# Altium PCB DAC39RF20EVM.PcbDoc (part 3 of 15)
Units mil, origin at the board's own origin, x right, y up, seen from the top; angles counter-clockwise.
Board outline 6200 x 2716.54 mil, 16 copper layers (Top Layer, L2 GND, L3 PWR, L4 GND, L5 PWR, L6 GND, L7 SIG, L8 GND, L9 GND, L10 SIG, L11 GND, L12 PWR, L13 GND, L14 PWR, L15 GND, Bottom Layer), stack 76.97 mil thick; 766 components, 495 nets, 3414 pads, 2373 vias.
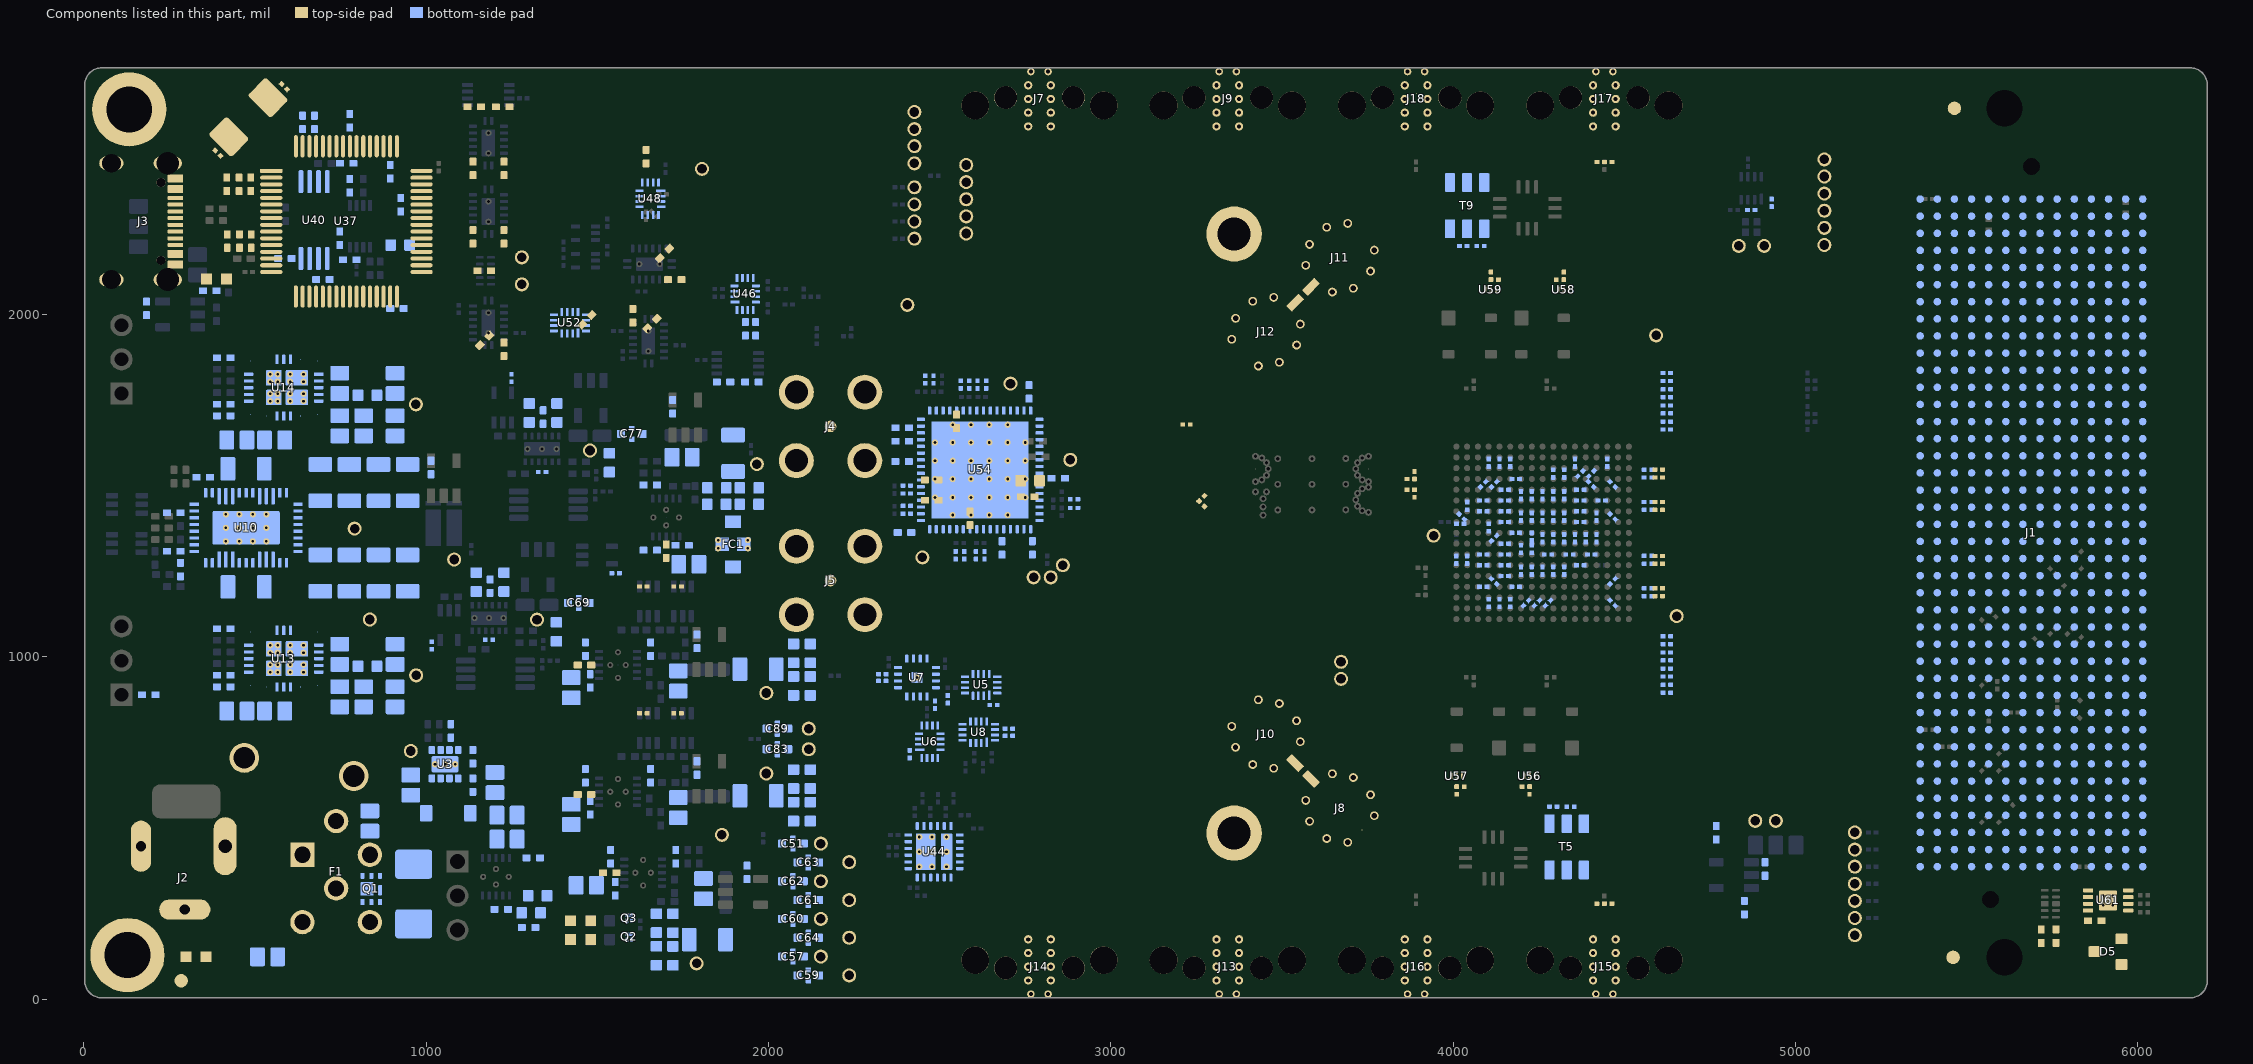
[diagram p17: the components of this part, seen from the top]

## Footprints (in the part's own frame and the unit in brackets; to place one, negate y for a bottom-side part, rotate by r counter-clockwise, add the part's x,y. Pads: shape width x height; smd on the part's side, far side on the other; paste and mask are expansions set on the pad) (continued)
HiRose-HK-LR-SR2-SWM1092-04A-MicroStirp-6mil-Female-Backdrill [mil]
  round 1 smd paste-100 mask+1.97: 1(75,0)
  round 22 hole 12 mask+1.97: 2(11,-25) 3(11,25)
  round 24 hole 12 mask+1.97: 2(51,-33) 2(91,-33) 3(51,33) 3(91,33) 3(131,-33) 3(131,33) 3(171,-33) 3(171,33)
  round 1 smd mask+1.97: 2(93.75,-131.66) 3(93.75,131.66)
  round 81 hole 81 mask+15.75: 2(110,-187.5) 3(110,187.5)
  round 1 on Mid1 mask+2.76: 3(86.25,0)
  round 66.93 hole 66.93 mask+15.75: 4(87,98.5) 4(87,-98.5)
  Top Layer region: 0,3.5 50,6.15 150,6.15 150,-6.15 50,-6.15 0,-3.5
  Top Layer region: 0,-249.82 0,-13.5 11.24,-13.5 14.57,-14.16 17.4,-16.05 17.4,-16.05 22.5,-21.15 187.5,-21.15 187.5,-249.82
  Top Layer region: 0,249.83 0,13.5 11.24,13.5 14.57,14.16 17.4,16.05 17.4,16.05 22.5,21.15 187.5,21.15 187.5,249.83
  L2 GND pour cut-out: 157,33 158.07,27.64 161.1,23.1 165.64,20.07 171,19 171,19 176.36,20.07 180.9,23.1 183.93,27.64 185,33 185,33 183.93,38.36 180.9,42.9 176.36,45.93 171,47 171,47 165.64,45.93 161.1,42.9 158.07,38.36 157,33
  L2 GND pour cut-out: 157,-33 158.07,-38.36 161.1,-42.9 165.64,-45.93 171,-47 171,-47 176.36,-45.93 180.9,-42.9 183.93,-38.36 185,-33 185,-33 183.93,-27.64 180.9,-23.1 176.36,-20.07 171,-19 171,-19 165.64,-20.07 161.1,-23.1 158.07,-27.64 157,-33
  L2 GND pour cut-out: 117,33 118.07,27.64 121.1,23.1 125.64,20.07 131,19 131,19 136.36,20.07 140.9,23.1 143.93,27.64 145,33 145,33 143.93,38.36 140.9,42.9 136.36,45.93 131,47 131,47 125.64,45.93 121.1,42.9 118.07,38.36 117,33
  L2 GND pour cut-out: 117,-33 118.07,-38.36 121.1,-42.9 125.64,-45.93 131,-47 131,-47 136.36,-45.93 140.9,-42.9 143.93,-38.36 145,-33 145,-33 143.93,-27.64 140.9,-23.1 136.36,-20.07 131,-19 131,-19 125.64,-20.07 121.1,-23.1 118.07,-27.64 117,-33
  L2 GND pour cut-out: 77,33 78.07,27.64 81.1,23.1 85.64,20.07 91,19 91,19 96.36,20.07 100.9,23.1 103.93,27.64 105,33 105,33 103.93,38.36 100.9,42.9 96.36,45.93 91,47 91,47 85.64,45.93 81.1,42.9 78.07,38.36 77,33
  L2 GND pour cut-out: 77,-33 78.07,-38.36 81.1,-42.9 85.64,-45.93 91,-47 91,-47 96.36,-45.93 100.9,-42.9 103.93,-38.36 105,-33 105,-33 103.93,-27.64 100.9,-23.1 96.36,-20.07 91,-19 91,-19 85.64,-20.07 81.1,-23.1 78.07,-27.64 77,-33
  L2 GND pour cut-out: 37,33 38.07,27.64 41.1,23.1 45.64,20.07 51,19 51,19 56.36,20.07 60.9,23.1 63.93,27.64 65,33 65,33 63.93,38.36 60.9,42.9 56.36,45.93 51,47 51,47 45.64,45.93 41.1,42.9 38.07,38.36 37,33
  L2 GND pour cut-out: 37,-33 38.07,-38.36 41.1,-42.9 45.64,-45.93 51,-47 51,-47 56.36,-45.93 60.9,-42.9 63.93,-38.36 65,-33 65,-33 63.93,-27.64 60.9,-23.1 56.36,-20.07 51,-19 51,-19 45.64,-20.07 41.1,-23.1 38.07,-27.64 37,-33
  L2 GND pour cut-out: -3,25 -1.93,19.64 1.1,15.1 5.64,12.07 11,11 11,11 16.36,12.07 20.9,15.1 23.93,19.64 25,25 25,25 23.93,30.36 20.9,34.9 16.36,37.93 11,39 11,39 5.64,37.93 1.1,34.9 -1.93,30.36 -3,25
  L2 GND pour cut-out: -3,-25 -1.93,-30.36 1.1,-34.9 5.64,-37.93 11,-39 11,-39 16.36,-37.93 20.9,-34.9 23.93,-30.36 25,-25 25,-25 23.93,-19.64 20.9,-15.1 16.36,-12.07 11,-11 11,-11 5.64,-12.07 1.1,-15.1 -1.93,-19.64 -3,-25
  L2 GND region: 187.5,-249.82 187.5,249.83 -15,249.83 -15,-249.82
  Bottom Layer pour cut-out: 171,16 164.49,17.29 158.98,20.98 155.29,26.49 154,33 154,33 155.29,39.51 158.98,45.02 164.49,48.71 171,50 171,50 177.51,48.71 183.02,45.02 186.71,39.51 188,33 188,33 186.71,26.49 183.02,20.98 177.51,17.29 171,16
  Bottom Layer pour cut-out: 171,-50 164.49,-48.71 158.98,-45.02 155.29,-39.51 154,-33 154,-33 155.29,-26.49 158.98,-20.98 164.49,-17.29 171,-16 171,-16 177.51,-17.29 183.02,-20.98 186.71,-26.49 188,-33 188,-33 186.71,-39.51 183.02,-45.02 177.51,-48.71 171,-50
  Bottom Layer pour cut-out: 131,-50 124.49,-48.71 118.98,-45.02 115.29,-39.51 114,-33 114,-33 115.29,-26.49 118.98,-20.98 124.49,-17.29 131,-16 131,-16 137.51,-17.29 143.02,-20.98 146.71,-26.49 148,-33 148,-33 146.71,-39.51 143.02,-45.02 137.51,-48.71 131,-50
  Bottom Layer pour cut-out: 91,-50 84.49,-48.71 78.98,-45.02 75.29,-39.51 74,-33 74,-33 75.29,-26.49 78.98,-20.98 84.49,-17.29 91,-16 91,-16 97.51,-17.29 103.02,-20.98 106.71,-26.49 108,-33 108,-33 106.71,-39.51 103.02,-45.02 97.51,-48.71 91,-50
  Bottom Layer pour cut-out: 51,-50 44.49,-48.71 38.98,-45.02 35.29,-39.51 34,-33 34,-33 35.29,-26.49 38.98,-20.98 44.49,-17.29 51,-16 51,-16 57.51,-17.29 63.02,-20.98 66.71,-26.49 68,-33 68,-33 66.71,-39.51 63.02,-45.02 57.51,-48.71 51,-50
  Bottom Layer pour cut-out: 51,16 44.49,17.29 38.98,20.98 35.29,26.49 34,33 34,33 35.29,39.51 38.98,45.02 44.49,48.71 51,50 51,50 57.51,48.71 63.02,45.02 66.71,39.51 68,33 68,33 66.71,26.49 63.02,20.98 57.51,17.29 51,16
  Bottom Layer pour cut-out: 91,16 84.49,17.29 78.98,20.98 75.29,26.49 74,33 74,33 75.29,39.51 78.98,45.02 84.49,48.71 91,50 91,50 97.51,48.71 103.02,45.02 106.71,39.51 108,33 108,33 106.71,26.49 103.02,20.98 97.51,17.29 91,16
  Bottom Layer pour cut-out: 131,16 124.49,17.29 118.98,20.98 115.29,26.49 114,33 114,33 115.29,39.51 118.98,45.02 124.49,48.71 131,50 131,50 137.51,48.71 143.02,45.02 146.71,39.51 148,33 148,33 146.71,26.49 143.02,20.98 137.51,17.29 131,16
  Bottom Layer pour cut-out: 11,-42 4.49,-40.71 -1.02,-37.02 -4.71,-31.51 -6,-25 -6,-25 -4.71,-18.49 -1.02,-12.98 4.49,-9.29 11,-8 11,-8 17.51,-9.29 23.02,-12.98 26.71,-18.49 28,-25 28,-25 26.71,-31.51 23.02,-37.02 17.51,-40.71 11,-42
  Bottom Layer pour cut-out: 11,8 4.49,9.29 -1.02,12.98 -4.71,18.49 -6,25 -6,25 -4.71,31.51 -1.02,37.02 4.49,40.71 11,42 11,42 17.51,40.71 23.02,37.02 26.71,31.51 28,25 28,25 26.71,18.49 23.02,12.98 17.51,9.29 11,8
  body extent -376,-165 157,165, height 132
IEC_HotSurface_Small [mil]
  silkscreen extent -107,-93 107,92
Keystone5010 [mil] "Keystone Multipurpose loops"
  round 87 hole 63: 1(0,0)
  silkscreen extent -70,-70 70,70, body extent -63,-63 63,62, height 319
Keystone5125 [mil] "Keystone Multipurpose loops"
  round 87 hole 63: 1(0,0)
  silkscreen extent -70,-70 70,70, body extent -63,-63 63,62, height 319
Keystone_1797B [mm] "HEX STANDOFF 2-56 ALUMINUM 1/4\""
  round 4.1 hole 2.45 unplated mask+0: 4(0,0)
  body extent -2.29,-2.22 2.29,2.22, height 6.35
Label_650x200 [mil] "Thermal Transfer Label"
  silkscreen extent -325,-100 325,100
LED_LTST-C190-Green [mm] "Lite-On"
  rect 0.8x0.8 smd: 1(-0.75,0) 2(0.75,0)
  silkscreen extent -1.1,-0.8 1.8,0.8, body extent -0.85,-0.45 0.85,0.45, height 0.91
LED_LTST-C190-Red [mm] "Lite-On"
  rect 0.8x0.8 smd: 1(-0.75,0) 2(0.75,0)
  silkscreen extent -1.1,-0.8 1.8,0.8, body extent -0.85,-0.45 0.85,0.45, height 0.91
LQFP64-MFG [mm]
  rrect33% 1.65x0.3 smd paste+0 mask+0.05: 1(-5.575,3.75)
  rrect100% 1.65x0.3 smd paste+0 mask+0.05: 2(-5.575,3.25) 3(-5.575,2.75) 4(-5.575,2.25) 5(-5.575,1.75) 6(-5.575,1.25) 7(-5.575,0.75) 8(-5.575,0.25) 9(-5.575,-0.25) 10(-5.575,-0.75) 11(-5.575,-1.25) 12(-5.575,-1.75) 13(-5.575,-2.25) 14(-5.575,-2.75) 15(-5.575,-3.25) 16(-5.575,-3.75) 33(5.575,-3.75) 34(5.575,-3.25) 35(5.575,-2.75) 36(5.575,-2.25) 37(5.575,-1.75) 38(5.575,-1.25) 39(5.575,-0.75) 40(5.575,-0.25) 41(5.575,0.25) 42(5.575,0.75) 43(5.575,1.25) 44(5.575,1.75) 45(5.575,2.25) 46(5.575,2.75) 47(5.575,3.25) 48(5.575,3.75)
  rrect100% 0.3x1.65 smd paste+0 mask+0.05: 17(-3.75,-5.575) 18(-3.25,-5.575) 19(-2.75,-5.575) 20(-2.25,-5.575) 21(-1.75,-5.575) 22(-1.25,-5.575) 23(-0.75,-5.575) 24(-0.25,-5.575) 25(0.25,-5.575) 26(0.75,-5.575) 27(1.25,-5.575) 28(1.75,-5.575) 29(2.25,-5.575) 30(2.75,-5.575) 31(3.25,-5.575) 32(3.75,-5.575) 49(3.75,5.575) 50(3.25,5.575) 51(2.75,5.575) 52(2.25,5.575) 53(1.75,5.575) 54(1.25,5.575) 55(0.75,5.575) 56(0.25,5.575) 57(-0.25,5.575) 58(-0.75,5.575) 59(-1.25,5.575) 60(-1.75,5.575) 61(-2.25,5.575) 62(-2.75,5.575) 63(-3.25,5.575) 64(-3.75,5.575)
  silkscreen extent -7.12,-5.05 5.05,5.05, body extent -6.5,-6.5 6.5,6.5, height 0.25
MABA-011108 [mm]
  rrect20% 1.4x0.76 smd mask+0.05: 1(-1.715,1.27) 2(-1.715,0) 3(-1.715,-1.27) 4(1.715,-1.27) 5(1.715,0) 6(1.715,1.27)
  silkscreen extent -2.25,1.85 -2.15,1.95, body extent -1.91,-1.91 1.91,1.91, height 3.42
Molex_0853050232 [mm] "Plug, 50 Ohm, Straight, SMT"
  rrect17% 0.6x1.3 smd: 1(0,0)
  round 0.654 hole 0.4 mask+0.05: 2(-2.3,-2.15) 2(-2.3,-3.95) 2(-1.4,-5.25) 2(-1.4,-0.85) 2(1.4,-5.25) 2(1.4,-0.85) 2(2.3,-2.15) 2(2.3,-3.95)
  round 0.025 smd: 2(0,-5.35)
  Top Layer pour cut-out: -0.33,0.699 -0.33,-0.698 0.33,-0.698 0.33,0.698
  Top Layer pour cut-out: 0.998,-1.315 0.998,-0.45 -0.998,-0.45 -0.998,-1.321 -1.679,-1.973 -1.986,-2.865 -1.849,-3.798 -1.3,-4.565 -0.461,-4.995 0.482,-4.992 1.319,-4.557 1.864,-3.787 1.995,-2.854 1.683,-1.963 0.998,-1.315
  Top Layer region: -2.6,-5.65 -2.6,-0.45 -1,-0.45 -1,-1.318 -1.732,-2.05 -2,-3.05 -1.732,-4.05 -1,-4.782 0,-5.05 1,-4.782 1.732,-4.05 2,-3.05 1.732,-2.05 1,-1.318 1,-1.318 1,-0.45 2.6,-0.45 2.6,-5.65
  L2 GND pour cut-out: -0.33,0.699 -0.33,-0.698 0.33,-0.698 0.33,0.698
  L2 GND pour cut-out: 0.998,-1.315 0.998,-0.45 -0.998,-0.45 -0.998,-1.321 -1.679,-1.973 -1.986,-2.865 -1.849,-3.798 -1.3,-4.565 -0.461,-4.995 0.482,-4.992 1.319,-4.557 1.864,-3.787 1.995,-2.854 1.683,-1.963 0.998,-1.315
  L2 GND pour cut-out: 0.998,-1.315 0.998,-0.45 -0.998,-0.45 -0.998,-1.321 -1.679,-1.973 -1.986,-2.865 -1.849,-3.798 -1.3,-4.565 -0.461,-4.995 0.482,-4.992 1.319,-4.557 1.864,-3.787 1.995,-2.854 1.683,-1.963 0.998,-1.315
  L3 PWR pour cut-out: 0.998,-1.315 0.998,-0.45 -0.998,-0.45 -0.998,-1.321 -1.679,-1.973 -1.986,-2.865 -1.849,-3.798 -1.3,-4.565 -0.461,-4.995 0.482,-4.992 1.319,-4.557 1.864,-3.787 1.995,-2.854 1.683,-1.963 0.998,-1.315
  body extent -2.5,-5.55 2.5,0.45, height 4.1
NFM18PC [mm]
  rrect20% 0.6x0.6 smd mask+0.05: 1(-0.8,0) 3(0.8,0)
  rrect20% 0.4x0.4 smd mask+0.05: 2(0,-0.4) 2(0,0.4)
  body extent -0.8,-0.4 0.8,0.4, height 1.35
NFM31PC [mm]
  rrect10% 0.95x1.2 smd paste+0: 1(-1.675,0) 3(1.675,0)
  round 0.2 / inner round 0.454 / far side round 0.454 hole 0.2 mask+0.05: 2(-0.305,-1.105) 2(-0.305,1.105) 2(0.305,-1.105) 2(0.305,1.105)
  rrect10% 1x1 smd paste+0: 2(0,-0.8) 2(0,0.8)
  body extent -1.7,-0.9 1.7,0.9, height 1.5
NKD0064A [mm] "QFN, 64-Leads, Body 9x9mm, Pitch 0.5mm"
  rrect40% 0.6x0.25 smd mask+0.07: 1(-4.4,3.75) 2(-4.4,3.25) 3(-4.4,2.75) 4(-4.4,2.25) 5(-4.4,1.75) 6(-4.4,1.25) 7(-4.4,0.75) 8(-4.4,0.25) 9(-4.4,-0.25) 10(-4.4,-0.75) 11(-4.4,-1.25) 12(-4.4,-1.75) 13(-4.4,-2.25) 14(-4.4,-2.75) 15(-4.4,-3.25) 16(-4.4,-3.75) 33(4.4,-3.75) 34(4.4,-3.25) 35(4.4,-2.75) 36(4.4,-2.25) 37(4.4,-1.75) 38(4.4,-1.25) 39(4.4,-0.75) 40(4.4,-0.25) 41(4.4,0.25) 42(4.4,0.75) 43(4.4,1.25) 44(4.4,1.75) 45(4.4,2.25) 46(4.4,2.75) 47(4.4,3.25) 48(4.4,3.75)
  rrect40% 0.25x0.6 smd mask+0.07: 17(-3.75,-4.4) 18(-3.25,-4.4) 19(-2.75,-4.4) 20(-2.25,-4.4) 21(-1.75,-4.4) 22(-1.25,-4.4) 23(-0.75,-4.4) 24(-0.25,-4.4) 25(0.25,-4.4) 26(0.75,-4.4) 27(1.25,-4.4) 28(1.75,-4.4) 29(2.25,-4.4) 30(2.75,-4.4) 31(3.25,-4.4) 32(3.75,-4.4) 49(3.75,4.4) 50(3.25,4.4) 51(2.75,4.4) 52(2.25,4.4) 53(1.75,4.4) 54(1.25,4.4) 55(0.75,4.4) 56(0.25,4.4) 57(-0.25,4.4) 58(-0.75,4.4) 59(-1.25,4.4) 60(-1.75,4.4) 61(-2.25,4.4) 62(-2.75,4.4) 63(-3.25,4.4) 64(-3.75,4.4)
  round 0.454 hole 0.2 mask+0.102: 65(-3.35,-2.04) 65(-3.35,-0.68) 65(-3.35,0.68) 65(-3.35,2.04) 65(-2.04,-3.35) 65(-2.04,-2.04) 65(-2.04,-0.68) 65(-2.04,0.68) 65(-2.04,2.04) 65(-2.04,3.35) 65(-0.68,-3.35) 65(-0.68,-2.04) 65(-0.68,-0.68) 65(-0.68,0.68) 65(-0.68,2.04) 65(-0.68,3.35) 65(0.68,-3.35) 65(0.68,-2.04) 65(0.68,-0.68) 65(0.68,0.68) 65(0.68,2.04) 65(0.68,3.35) 65(2.04,-3.35) 65(2.04,-2.04) 65(2.04,-0.68) 65(2.04,0.68) 65(2.04,2.04) 65(2.04,3.35) 65(3.35,-2.04) 65(3.35,-0.68) 65(3.35,0.68) 65(3.35,2.04)
  rrect1% 7.2x7.2 smd paste-3.6 mask+0.07: 65(0,0)
  silkscreen extent -4.65,-4.65 4.65,4.65, body extent -4.55,-4.55 4.55,4.55, height 0.8
ProbePoint_TH_40mil [mil]
  round 41 hole 28: 1(0,0)
RAPC722X [mm] "Conn_DC Jack"
  oval 1.7x4.3 hole 1.01 slot 3.56 at 90 deg: 1(6.248,0)
  oval 1.5x3.8 hole 0.76 slot 3.05 at 90 deg: 2(0,0)
  oval 3.8x1.5 hole 0.76 slot 3.05 at 0 deg: 3(3.251,-4.7)
  silkscreen extent -0.12,-4.57 6.98,8.72, body extent -7.36,-4.97 7.12,4.56, height 10.92
RDB0051A [mm]
  round 0.025 smd mask+0.05: 1(-2.54,3.625) 15(-2.54,-3.625) 24(2.54,-3.625) 38(2.54,3.625)
  rrect30% 0.7x0.25 smd paste+0 mask+0.05: 2(-2.6,3) 3(-2.6,2.5) 7(-2.6,0.5) 8(-2.6,0) 9(-2.6,-0.5) 13(-2.6,-2.5) 14(-2.6,-3) 25(2.6,-3) 26(2.6,-2.5) 30(2.6,-0.5) 31(2.6,0) 32(2.6,0.5) 36(2.6,2.5) 37(2.6,3)
  rrect30% 1.2x0.25 smd paste+0 mask+0.05: 4(-2.35,2) 5(-2.35,1.5) 6(-2.35,1) 10(-2.35,-1) 11(-2.35,-1.5) 12(-2.35,-2) 27(2.35,-2) 28(2.35,-1.5) 29(2.35,-1) 33(2.35,1) 34(2.35,1.5) 35(2.35,2)
  rrect30% 0.25x0.7 smd paste+0 mask+0.05: 16(-1.75,-3.85) 17(-1.25,-3.85) 18(-0.75,-3.85) 19(-0.25,-3.85) 20(0.25,-3.85) 21(0.75,-3.85) 22(1.25,-3.85) 23(1.75,-3.85) 39(1.75,3.85) 40(1.25,3.85) 41(0.75,3.85) 42(0.25,3.85) 43(-0.25,3.85) 44(-0.75,3.85) 45(-1.25,3.85) 46(-1.75,3.85)
  rrect10% 2.5x5 smd paste-5: 47(0,0)
  round 0.454 hole 0.2 mask+0.102: 48(-1,1.5) 48(0,1.5) 48(1,1.5) 49(-1,0.5) 49(0,0.5) 49(1,0.5) 50(-1,-0.5) 50(0,-0.5) 50(1,-0.5) 51(-1,-1.5) 51(0,-1.5) 51(1,-1.5)
  Top Layer region: -2.955,3.624 -2.955,3.425 -2.951,3.406 -2.94,3.389 -2.923,3.379 -2.904,3.375 -2.904,3.375 -2.175,3.375 -2.156,3.379 -2.139,3.39 -2.128,3.407 -2.125,3.426 -2.125,3.426 -2.125,3.825 -2.129,3.844 -2.14,3.861 -2.156,3.872 -2.176,3.875 -2.176,3.875 -2.375,3.875 -2.394,3.871 -2.411,3.86 -2.421,3.844 -2.425,3.824 -2.425,3.824 -2.425,3.726 -2.428,3.707 -2.439,3.69 -2.456,3.679 -2.475,3.675 -2.475,3.675 -2.9,3.675 -2.921,3.673 -2.939,3.662 -2.951,3.645 -2.955,3.624
  Top Layer region: 2.955,3.624 2.955,3.425 2.951,3.406 2.94,3.389 2.924,3.379 2.904,3.375 2.904,3.375 2.175,3.375 2.156,3.379 2.139,3.39 2.129,3.407 2.125,3.426 2.125,3.426 2.125,3.825 2.129,3.844 2.14,3.861 2.157,3.872 2.176,3.875 2.176,3.875 2.375,3.875 2.394,3.871 2.411,3.86 2.422,3.844 2.425,3.824 2.425,3.824 2.425,3.726 2.429,3.707 2.439,3.69 2.456,3.679 2.475,3.675 2.475,3.675 2.9,3.675 2.921,3.673 2.939,3.662 2.951,3.645 2.955,3.624
  Top Layer region: 2.955,-3.624 2.955,-3.425 2.951,-3.406 2.94,-3.389 2.924,-3.378 2.904,-3.375 2.904,-3.375 2.175,-3.375 2.156,-3.379 2.139,-3.39 2.129,-3.406 2.125,-3.426 2.125,-3.426 2.125,-3.825 2.129,-3.844 2.14,-3.861 2.157,-3.871 2.176,-3.875 2.176,-3.875 2.375,-3.875 2.394,-3.871 2.411,-3.86 2.422,-3.843 2.425,-3.824 2.425,-3.824 2.425,-3.726 2.429,-3.706 2.439,-3.69 2.456,-3.679 2.475,-3.675 2.475,-3.675 2.9,-3.675 2.921,-3.673 2.939,-3.662 2.951,-3.645 2.955,-3.624
  Top Layer region: -2.955,-3.624 -2.955,-3.425 -2.951,-3.406 -2.94,-3.389 -2.923,-3.378 -2.904,-3.375 -2.904,-3.375 -2.175,-3.375 -2.156,-3.379 -2.139,-3.39 -2.128,-3.406 -2.125,-3.426 -2.125,-3.426 -2.125,-3.825 -2.129,-3.844 -2.14,-3.861 -2.156,-3.871 -2.176,-3.875 -2.176,-3.875 -2.375,-3.875 -2.394,-3.871 -2.411,-3.86 -2.421,-3.843 -2.425,-3.824 -2.425,-3.824 -2.425,-3.726 -2.428,-3.706 -2.439,-3.69 -2.456,-3.679 -2.475,-3.675 -2.475,-3.675 -2.9,-3.675 -2.921,-3.673 -2.939,-3.662 -2.951,-3.645 -2.955,-3.624
  silkscreen extent -3.33,-4.3 2.8,4.3, body extent -2.75,-4 2.75,4, height 1.8
RDU0028A [mm]
  round 0.025 smd mask+0.05: 1(-1.987,2.487) 2(-2.1,1.25) 6(-2.1,-1.25) 7(-1.987,-2.488) 13(1.987,-2.488) 14(2.1,-1.25) 18(2.1,1.25) 19(1.988,2.488)
  rrect40% 0.7x0.25 smd paste+0 mask+0.05: 3(-2.1,0.5) 4(-2.1,0) 5(-2.1,-0.5) 15(2.1,-0.5) 16(2.1,0) 17(2.1,0.5)
  rrect40% 0.25x0.7 smd paste+0 mask+0.05: 8(-1,-2.6) 9(-0.5,-2.6) 10(0,-2.6) 11(0.5,-2.6) 12(1,-2.6) 20(1,2.6) 21(0.5,2.6) 22(0,2.6) 23(-0.5,2.6) 24(-1,2.6)
  round 0.454 hole 0.2 mask+0.102: 25(-1,1) 25(-1,0.45) 25(-0.45,1) 25(-0.45,0.45) 26(-1,-1.475) 26(-1,-0.475) 26(-0.45,-1.475) 26(-0.45,-0.475) 27(0.45,-1.475) 27(0.45,-0.475) 27(1,-1.475) 27(1,-0.475) 28(0.45,1) 28(0.45,0.45) 28(1,1) 28(1,0.45)
  rrect9% 1.15x1.15 smd paste-1000 mask+0.05: 25(-0.725,0.725) 28(0.725,0.725)
  rrect9% 1.15x1.65 smd paste-1000 mask+0.05: 26(-0.725,-0.975) 27(0.725,-0.975)
  Top Layer region: -1.575,2.95 -1.55,2.943 -1.532,2.925 -1.525,2.9 -1.525,2.9 -1.525,2.075 -1.529,2.056 -1.54,2.04 -1.556,2.029 -1.575,2.025 -1.575,2.025 -2.4,2.025 -2.423,2.033 -2.439,2.051 -2.445,2.075 -2.445,2.075 -2.45,2.225 -2.443,2.25 -2.425,2.268 -2.4,2.275 -2.4,2.275 -2.225,2.275 -2.187,2.283 -2.154,2.304 -2.133,2.337 -2.125,2.375 -2.125,2.375 -2.125,2.575 -2.118,2.6 -2.1,2.618 -2.075,2.625 -2.075,2.625 -1.875,2.625 -1.837,2.633 -1.804,2.654 -1.783,2.687 -1.775,2.725 -1.775,2.725 -1.775,2.9 -1.768,2.925 -1.75,2.943 -1.725,2.95 -1.725,2.95
  Top Layer region: 1.575,2.95 1.55,2.943 1.532,2.925 1.525,2.9 1.525,2.9 1.525,2.075 1.529,2.056 1.54,2.04 1.556,2.029 1.575,2.025 1.575,2.025 2.4,2.025 2.423,2.033 2.439,2.051 2.445,2.075 2.445,2.075 2.45,2.225 2.443,2.25 2.425,2.268 2.4,2.275 2.4,2.275 2.225,2.275 2.187,2.283 2.154,2.304 2.133,2.337 2.125,2.375 2.125,2.375 2.125,2.575 2.118,2.6 2.1,2.618 2.075,2.625 2.075,2.625 1.875,2.625 1.837,2.633 1.804,2.654 1.783,2.687 1.775,2.725 1.775,2.725 1.775,2.9 1.768,2.925 1.75,2.943 1.725,2.95 1.725,2.95
  Top Layer region: 2.4,0.875 1.8,0.875 1.775,0.882 1.757,0.9 1.75,0.925 1.75,0.925 1.75,1.575 1.754,1.594 1.765,1.61 1.781,1.621 1.8,1.625 1.8,1.625 2.4,1.625 2.419,1.621 2.435,1.61 2.446,1.594 2.45,1.575 2.45,1.575 2.45,1.425 2.443,1.4 2.425,1.382 2.4,1.375 2.4,1.375 2.225,1.375 2.187,1.367 2.154,1.346 2.133,1.313 2.125,1.275 2.125,1.275 2.125,1.225 2.138,1.175 2.175,1.138 2.225,1.125 2.225,1.125 2.4,1.125 2.419,1.121 2.435,1.11 2.446,1.094 2.45,1.075 2.45,1.075 2.45,0.925 2.443,0.9 2.425,0.882 2.4,0.875
  Top Layer region: 2.4,-1.625 1.8,-1.625 1.775,-1.618 1.757,-1.6 1.75,-1.575 1.75,-1.575 1.75,-0.925 1.754,-0.906 1.765,-0.89 1.781,-0.879 1.8,-0.875 1.8,-0.875 2.4,-0.875 2.419,-0.879 2.435,-0.89 2.446,-0.906 2.45,-0.925 2.45,-0.925 2.45,-1.075 2.443,-1.1 2.425,-1.118 2.4,-1.125 2.4,-1.125 2.225,-1.125 2.187,-1.133 2.154,-1.154 2.133,-1.187 2.125,-1.225 2.125,-1.225 2.125,-1.275 2.138,-1.325 2.175,-1.362 2.225,-1.375 2.225,-1.375 2.4,-1.375 2.419,-1.379 2.435,-1.39 2.446,-1.406 2.45,-1.425 2.45,-1.425 2.45,-1.575 2.443,-1.6 2.425,-1.618 2.4,-1.625
  Top Layer region: 1.575,-2.95 1.55,-2.943 1.532,-2.925 1.525,-2.9 1.525,-2.9 1.525,-2.075 1.529,-2.056 1.54,-2.04 1.556,-2.029 1.575,-2.025 1.575,-2.025 2.4,-2.025 2.423,-2.033 2.439,-2.051 2.445,-2.075 2.445,-2.075 2.45,-2.225 2.443,-2.25 2.425,-2.268 2.4,-2.275 2.4,-2.275 2.225,-2.275 2.187,-2.283 2.154,-2.304 2.133,-2.337 2.125,-2.375 2.125,-2.375 2.125,-2.575 2.118,-2.6 2.1,-2.618 2.075,-2.625 2.075,-2.625 1.875,-2.625 1.837,-2.633 1.804,-2.654 1.783,-2.687 1.775,-2.725 1.775,-2.725 1.775,-2.9 1.768,-2.925 1.75,-2.943 1.725,-2.95 1.725,-2.95
  Top Layer region: -1.575,-2.95 -1.55,-2.943 -1.532,-2.925 -1.525,-2.9 -1.525,-2.9 -1.525,-2.075 -1.529,-2.056 -1.54,-2.04 -1.556,-2.029 -1.575,-2.025 -1.575,-2.025 -2.4,-2.025 -2.423,-2.033 -2.439,-2.051 -2.445,-2.075 -2.445,-2.075 -2.45,-2.225 -2.443,-2.25 -2.425,-2.268 -2.4,-2.275 -2.4,-2.275 -2.225,-2.275 -2.187,-2.283 -2.154,-2.304 -2.133,-2.337 -2.125,-2.375 -2.125,-2.375 -2.125,-2.575 -2.118,-2.6 -2.1,-2.618 -2.075,-2.625 -2.075,-2.625 -1.875,-2.625 -1.837,-2.633 -1.804,-2.654 -1.783,-2.687 -1.775,-2.725 -1.775,-2.725 -1.775,-2.9 -1.768,-2.925 -1.75,-2.943 -1.725,-2.95 -1.725,-2.95
  Top Layer region: -2.4,-0.875 -1.8,-0.875 -1.775,-0.882 -1.757,-0.9 -1.75,-0.925 -1.75,-0.925 -1.75,-1.575 -1.754,-1.594 -1.765,-1.61 -1.781,-1.621 -1.8,-1.625 -1.8,-1.625 -2.4,-1.625 -2.419,-1.621 -2.435,-1.61 -2.446,-1.594 -2.45,-1.575 -2.45,-1.575 -2.45,-1.425 -2.443,-1.4 -2.425,-1.382 -2.4,-1.375 -2.4,-1.375 -2.225,-1.375 -2.187,-1.367 -2.154,-1.346 -2.133,-1.313 -2.125,-1.275 -2.125,-1.275 -2.125,-1.225 -2.138,-1.175 -2.175,-1.138 -2.225,-1.125 -2.225,-1.125 -2.4,-1.125 -2.419,-1.121 -2.435,-1.11 -2.446,-1.094 -2.45,-1.075 -2.45,-1.075 -2.45,-0.925 -2.443,-0.9 -2.425,-0.882 -2.4,-0.875
  Top Layer region: -2.4,1.625 -1.8,1.625 -1.781,1.621 -1.765,1.61 -1.754,1.594 -1.75,1.575 -1.75,1.575 -1.75,0.925 -1.754,0.906 -1.765,0.89 -1.781,0.879 -1.8,0.875 -1.8,0.875 -2.4,0.875 -2.419,0.879 -2.435,0.89 -2.446,0.906 -2.45,0.925 -2.45,0.925 -2.45,1.075 -2.443,1.1 -2.425,1.118 -2.4,1.125 -2.4,1.125 -2.225,1.125 -2.187,1.133 -2.154,1.154 -2.133,1.187 -2.125,1.225 -2.125,1.225 -2.125,1.275 -2.138,1.325 -2.175,1.362 -2.225,1.375 -2.225,1.375 -2.4,1.375 -2.419,1.379 -2.435,1.39 -2.446,1.406 -2.45,1.425 -2.45,1.425 -2.45,1.575 -2.443,1.6 -2.425,1.618 -2.4,1.625
  silkscreen extent -3.2,-3.13 2.63,3.13, body extent -2.25,-2.75 2.25,2.75, height 1.9
RGE0024M [mm]
  rrect42% 0.575x0.24 smd paste+0 mask+0.05: 1(-1.913,1.25) 2(-1.913,0.75) 3(-1.913,0.25) 4(-1.913,-0.25) 5(-1.913,-0.75) 6(-1.913,-1.25) 13(1.913,-1.25) 14(1.913,-0.75) 15(1.913,-0.25) 16(1.913,0.25) 17(1.913,0.75) 18(1.913,1.25)
  rrect42% 0.24x0.575 smd paste+0 mask+0.05: 7(-1.25,-1.913) 8(-0.75,-1.913) 9(-0.25,-1.913) 10(0.25,-1.913) 11(0.75,-1.913) 12(1.25,-1.913) 19(1.25,1.913) 20(0.75,1.913) 21(0.25,1.913) 22(-0.25,1.913) 23(-0.75,1.913) 24(-1.25,1.913)
  round 0.457 hole 0.2 mask+0.07: 25(-1.1,0.15) 25(-1.1,1.1) 25(0,0.15) 25(0,1.1) 25(1.1,0.15) 25(1.1,1.1) 26(-1.1,-0.925) 26(0,-0.925) 26(1.1,-0.925)
  rrect7% 2.7x1.45 smd paste-1000 mask+0.05: 25(0,0.625)
  rrect12% 2.7x0.85 smd paste-1000 mask+0.05: 26(0,-0.925)
  silkscreen extent -2.65,-2.05 2.05,2.05, body extent -2,-2 2,2, height 1
RSV0016A [mm] "QFN, 16-Leads, Body 1.8x2.6mm, Pitch 0.4mm, TI Recommended"
  rrect25% 0.7x0.2 smd mask+0.05: 1(-0.75,0.6)
  rrect25% 0.6x0.2 smd mask+0.05: 2(-0.8,0.2) 3(-0.8,-0.2) 4(-0.8,-0.6) 9(0.8,-0.6) 10(0.8,-0.2) 11(0.8,0.2) 12(0.8,0.6)
  rrect25% 0.2x0.6 smd mask+0.05: 5(-0.6,-1.2) 6(-0.2,-1.2) 7(0.2,-1.2) 8(0.6,-1.2) 13(0.6,1.2) 14(0.2,1.2) 15(-0.2,1.2) 16(-0.6,1.2)
  silkscreen extent -1.08,-1.33 1.08,1.45, body extent -0.85,-1.31 0.85,1.31, height 0.49
RTE0016D [mm]
  rrect42% 0.6x0.24 smd paste+0 mask+0.07: 1(-1.4,0.75) 2(-1.4,0.25) 3(-1.4,-0.25) 4(-1.4,-0.75) 9(1.4,-0.75) 10(1.4,-0.25) 11(1.4,0.25) 12(1.4,0.75)
  rrect42% 0.24x0.6 smd paste+0 mask+0.07: 5(-0.75,-1.4) 6(-0.25,-1.4) 7(0.25,-1.4) 8(0.75,-1.4) 13(0.75,1.4) 14(0.25,1.4) 15(-0.25,1.4) 16(-0.75,1.4)
  round 0.454 hole 0.2 mask+0.05: 17(0,0)
  rrect6% 0.8x0.8 smd paste-0.04 mask+0: 17(0,0)
  silkscreen extent -2.06,-1.55 1.55,1.55, body extent -1.5,-1.5 1.5,1.5, height 0.8
Samtec_ASP-184330-01 [mil] "Terminal Array, 1.27mm, 40x14, SMT"
  round 22 smd: A1(975,225) A2(925,225) A3(875,225) A4(825,225) A5(775,225) A6(725,225) A7(675,225) A8(625,225) A9(575,225) A10(525,225) A11(475,225) A12(425,225) A13(375,225) A14(325,225) A15(275,225) A16(225,225) A17(175,225) A18(125,225) A19(75,225) A20(25,225) A21(-25,225) A22(-75,225) A23(-125,225) A24(-175,225) A25(-225,225) A26(-275,225) A27(-325,225) A28(-375,225) A29(-425,225) A30(-475,225) A31(-525,225) A32(-575,225) A33(-625,225) A34(-675,225) A35(-725,225) A36(-775,225) A37(-825,225) A38(-875,225) A39(-925,225) A40(-975,225) B1(975,175) B2(925,175) B3(875,175) B4(825,175) B5(775,175) B6(725,175) B7(675,175) B8(625,175) B9(575,175) B10(525,175) B11(475,175) B12(425,175) B13(375,175) B14(325,175) B15(275,175) B16(225,175) B17(175,175) B18(125,175) B19(75,175) B20(25,175) B21(-25,175) B22(-75,175) B23(-125,175) B24(-175,175) B25(-225,175) B26(-275,175) B27(-325,175) B28(-375,175) B29(-425,175) B30(-475,175) B31(-525,175) B32(-575,175) B33(-625,175) B34(-675,175) B35(-725,175) B36(-775,175) B37(-825,175) B38(-875,175) B39(-925,175) B40(-975,175) C1(975,125) C2(925,125) C3(875,125) C4(825,125) C5(775,125) C6(725,125) C7(675,125) C8(625,125) C9(575,125) C10(525,125) C11(475,125) C12(425,125) C13(375,125) C14(325,125) C15(275,125) C16(225,125) C17(175,125) C18(125,125) C19(75,125) C20(25,125) C21(-25,125) C22(-75,125) C23(-125,125) C24(-175,125) C25(-225,125) C26(-275,125) C27(-325,125) C28(-375,125) C29(-425,125) C30(-475,125) C31(-525,125) C32(-575,125) C33(-625,125) C34(-675,125) C35(-725,125) C36(-775,125) C37(-825,125) C38(-875,125) C39(-925,125) C40(-975,125) D1(975,75) D2(925,75) D3(875,75) D4(825,75) D5(775,75) D6(725,75) D7(675,75) D8(625,75) D9(575,75) D10(525,75) D11(475,75) D12(425,75) D13(375,75) D14(325,75) D15(275,75) D16(225,75) D17(175,75) D18(125,75) D19(75,75) D20(25,75) D21(-25,75) D22(-75,75) D23(-125,75) D24(-175,75) D25(-225,75) D26(-275,75) D27(-325,75) D28(-375,75) D29(-425,75) D30(-475,75) D31(-525,75) D32(-575,75) D33(-625,75) D34(-675,75) D35(-725,75) D36(-775,75) D37(-825,75) D38(-875,75) D39(-925,75) D40(-975,75) E1(975,25) E2(925,25) E3(875,25) E4(825,25) E5(775,25) E6(725,25) E7(675,25) E8(625,25) E9(575,25) E10(525,25) E11(475,25) E12(425,25) E13(375,25) E14(325,25) E15(275,25) E16(225,25) E17(175,25) E18(125,25) E19(75,25) E20(25,25) E21(-25,25) E22(-75,25) E23(-125,25) E24(-175,25) E25(-225,25) E26(-275,25) E27(-325,25) E28(-375,25) E29(-425,25) E30(-475,25) E31(-525,25) E32(-575,25) E33(-625,25) E34(-675,25) E35(-725,25) E36(-775,25) E37(-825,25) E38(-875,25) E39(-925,25) E40(-975,25) F1(975,-25) F2(925,-25) F3(875,-25) F4(825,-25) F5(775,-25) F6(725,-25) F7(675,-25) F8(625,-25) F9(575,-25) F10(525,-25) F11(475,-25) F12(425,-25) F13(375,-25) F14(325,-25) F15(275,-25) F16(225,-25) F17(175,-25) F18(125,-25) F19(75,-25) F20(25,-25) F21(-25,-25) F22(-75,-25) F23(-125,-25) F24(-175,-25) F25(-225,-25) F26(-275,-25) F27(-325,-25) F28(-375,-25) F29(-425,-25) F30(-475,-25) F31(-525,-25) F32(-575,-25) F33(-625,-25) F34(-675,-25) F35(-725,-25) F36(-775,-25) F37(-825,-25) F38(-875,-25) F39(-925,-25) F40(-975,-25) G1(975,-75) G2(925,-75) G3(875,-75) G4(825,-75) G5(775,-75) G6(725,-75) G7(675,-75) G8(625,-75) G9(575,-75) G10(525,-75) G11(475,-75) G12(425,-75) G13(375,-75) G14(325,-75) G15(275,-75) G16(225,-75) G17(175,-75) G18(125,-75) G19(75,-75) G20(25,-75) G21(-25,-75) G22(-75,-75) G23(-125,-75) G24(-175,-75) G25(-225,-75) G26(-275,-75) G27(-325,-75) G28(-375,-75) G29(-425,-75) G30(-475,-75) G31(-525,-75) G32(-575,-75) G33(-625,-75) G34(-675,-75) G35(-725,-75) G36(-775,-75) G37(-825,-75) G38(-875,-75) G39(-925,-75) G40(-975,-75) H1(975,-125) H2(925,-125) H3(875,-125) H4(825,-125) H5(775,-125) H6(725,-125) H7(675,-125) H8(625,-125) H9(575,-125) H10(525,-125) H11(475,-125) H12(425,-125) H13(375,-125) H14(325,-125) H15(275,-125) H16(225,-125) H17(175,-125) H18(125,-125) H19(75,-125) H20(25,-125) H21(-25,-125) H22(-75,-125) H23(-125,-125) H24(-175,-125) H25(-225,-125) H26(-275,-125) H27(-325,-125) H28(-375,-125) H29(-425,-125) H30(-475,-125) H31(-525,-125) H32(-575,-125) H33(-625,-125) H34(-675,-125) H35(-725,-125) H36(-775,-125) H37(-825,-125) H38(-875,-125) H39(-925,-125) H40(-975,-125) J1(975,-175) J2(925,-175) J3(875,-175) J4(825,-175) J5(775,-175) J6(725,-175) J7(675,-175) J8(625,-175) J9(575,-175) J10(525,-175) J11(475,-175) J12(425,-175) J13(375,-175) J14(325,-175) J15(275,-175) J16(225,-175) J17(175,-175) J18(125,-175) J19(75,-175) J20(25,-175) J21(-25,-175) J22(-75,-175) J23(-125,-175) J24(-175,-175) J25(-225,-175) J26(-275,-175) J27(-325,-175) J28(-375,-175) J29(-425,-175) J30(-475,-175) J31(-525,-175) J32(-575,-175) J33(-625,-175) J34(-675,-175) J35(-725,-175) J36(-775,-175) J37(-825,-175) J38(-875,-175) J39(-925,-175) J40(-975,-175) K1(975,-225) K2(925,-225) K3(875,-225) K4(825,-225) K5(775,-225) K6(725,-225) K7(675,-225) K8(625,-225) K9(575,-225) K10(525,-225) K11(475,-225) K12(425,-225) K13(375,-225) K14(325,-225) K15(275,-225) K16(225,-225) K17(175,-225) K18(125,-225) K19(75,-225) K20(25,-225) K21(-25,-225) K22(-75,-225) K23(-125,-225) K24(-175,-225) K25(-225,-225) K26(-275,-225) K27(-325,-225) K28(-375,-225) K29(-425,-225) K30(-475,-225) K31(-525,-225) K32(-575,-225) K33(-625,-225) K34(-675,-225) K35(-725,-225) K36(-775,-225) K37(-825,-225) K38(-875,-225) K39(-925,-225) K40(-975,-225) L1(975,-275) L2(925,-275) L3(875,-275) L4(825,-275) L5(775,-275) L6(725,-275) L7(675,-275) L8(625,-275) L9(575,-275) L10(525,-275) L11(475,-275) L12(425,-275) L13(375,-275) L14(325,-275) L15(275,-275) L16(225,-275) L17(175,-275) L18(125,-275) L19(75,-275) L20(25,-275) L21(-25,-275) L22(-75,-275) L23(-125,-275) L24(-175,-275) L25(-225,-275) L26(-275,-275) L27(-325,-275) L28(-375,-275) L29(-425,-275) L30(-475,-275) L31(-525,-275) L32(-575,-275) L33(-625,-275) L34(-675,-275) L35(-725,-275) L36(-775,-275) L37(-825,-275) L38(-875,-275) L39(-925,-275) L40(-975,-275) M1(975,-325) M2(925,-325) M3(875,-325) M4(825,-325) M5(775,-325) M6(725,-325) M7(675,-325) M8(625,-325) M9(575,-325) M10(525,-325) M11(475,-325) M12(425,-325) M13(375,-325) M14(325,-325) M15(275,-325) M16(225,-325) M17(175,-325) M18(125,-325) M19(75,-325) M20(25,-325) M21(-25,-325) M22(-75,-325) M23(-125,-325) M24(-175,-325) M25(-225,-325) M26(-275,-325) M27(-325,-325) M28(-375,-325) M29(-425,-325) M30(-475,-325) M31(-525,-325) M32(-575,-325) M33(-625,-325) M34(-675,-325) M35(-725,-325) M36(-775,-325) M37(-825,-325) M38(-875,-325) M39(-925,-325) M40(-975,-325) Y1(975,325) Y2(925,325) Y3(875,325) Y4(825,325) Y5(775,325) Y6(725,325) Y7(675,325) Y8(625,325) Y9(575,325) Y10(525,325) Y11(475,325) Y12(425,325) Y13(375,325) Y14(325,325) Y15(275,325) Y16(225,325) Y17(175,325) Y18(125,325) Y19(75,325) Y20(25,325) Y21(-25,325) Y22(-75,325) Y23(-125,325) Y24(-175,325) Y25(-225,325) Y26(-275,325) Y27(-325,325) Y28(-375,325) Y29(-425,325) Y30(-475,325) Y31(-525,325) Y32(-575,325) Y33(-625,325) Y34(-675,325) Y35(-725,325) Y36(-775,325) Y37(-825,325) Y38(-875,325) Y39(-925,325) Y40(-975,325) Z1(975,275) Z2(925,275) Z3(875,275) Z4(825,275) Z5(775,275) Z6(725,275) Z7(675,275) Z8(625,275) Z9(575,275) Z10(525,275) Z11(475,275) Z12(425,275) Z13(375,275) Z14(325,275) Z15(275,275) Z16(225,275) Z17(175,275) Z18(125,275) Z19(75,275) Z20(25,275) Z21(-25,275) Z22(-75,275) Z23(-125,275) Z24(-175,275) Z25(-225,275) Z26(-275,275) Z27(-325,275) Z28(-375,275) Z29(-425,275) Z30(-475,275) Z31(-525,275) Z32(-575,275) Z33(-625,275) Z34(-675,275) Z35(-725,275) Z36(-775,275) Z37(-825,275) Z38(-875,275) Z39(-925,275) Z40(-975,275)
  round 0 hole 105.91 unplated: ""(-1240,-79) ""(1240,-79)
  round 0 hole 50 unplated: ""(-1070.5,-120) ""(1070.5,0)
  silkscreen extent -1098,-389 1133,406, body extent -1098,-389 1133,389, height 289
SIL0008D [mm] "SIP, 8-Leads, Body 2.8x3.0mm, Pitch 0.65mm, Thermal Pad 1.9x1.1mm"
  rrect12% 1.04x0.85 on Bottom Paste: 0(0,-0.525) 0(0,0.525)
  rrect40% 0.6x0.5 smd paste-0.05 mask-0.05: 1(-1.05,0.975) 2(-1.05,0.325) 3(-1.05,-0.325) 4(-1.05,-0.975) 5(1.05,-0.975) 6(1.05,-0.325) 7(1.05,0.325) 8(1.05,0.975)
  round 0.457 hole 0.203 mask+0.05: 9(0,-0.75) 9(0,0) 9(0,0.75)
  rrect17% 1.2x2 smd paste-0.6 mask-0.05: 9(0,0)
  silkscreen extent -1.53,-1.63 1.53,1.63, body extent -1.4,-1.5 1.4,1.5, height 1.53
SMBJ15CA [mil]
  rrect20% 85x107.99 smd: 1(-87.01,0) 2(87.01,0)
  silkscreen extent -125,-79 125,79, body extent -104,-73 104,73, height 89
SOD-123 [mm] "On Semi recommended land pattern"
  rrect20% 0.915x1.22 smd: 1(-1.637,0) 2(1.637,0)
  silkscreen extent -2.74,-1.17 2.03,1.17, body extent -1.93,-0.9 1.93,0.9, height 1.35
SOT-323-DIO [mm]
  rrect21% 0.9x0.8 smd: 1(-1,0.95) 2(-1,-0.95) 3(1,0)
  silkscreen extent -1.14,-1.52 0.77,1.52, body extent -1.25,-1.5 1.24,1.5, height 1.2
SUSUMU_ATS1005 [mm]
  rrect20% 0.15x0.2 smd mask+0.05: 1(-0.145,0) 2(0.145,0)
  rrect20% 0.44x0.15 smd mask+0.05: 3(0,0.395) 3(0,-0.395)
  silkscreen extent -0.51,0.07 -0.41,0.17, body extent -0.26,-0.51 0.26,0.51, height 0.32
TDFN8 [mm]
  rrect30% 0.75x0.3 smd paste+0 mask+0.05: 1(-1.5,0.75) 2(-1.5,0.25) 3(-1.5,-0.25) 4(-1.5,-0.75) 5(1.478,-0.75) 6(1.478,-0.25) 7(1.478,0.25) 8(1.478,0.75)
  round 0.327 / inner round 0.454 / far side round 0.454 hole 0.2 mask+0.05: 9(-0.354,0.354) 9(-0.354,-0.354) 9(0.354,0.354) 9(0.354,-0.354)
  rrect10% 1.36x1.46 smd paste+0 mask+0.05: 9(0,0)
  silkscreen extent -1.56,1.07 -1.4,1.22, body extent -1.5,-1 1.5,1, height 0.75
TI_Stacked_Overlay_Small_Vertical [mil]
  silkscreen extent -66,-288 69,288
TI_Symbol_Overlay_Medium [mil]
  silkscreen extent -124,-122 124,120
TSSOP-8 [mm] "TSSOP, 8-Leads, Body 3.1x4.5mm (max), Pitch 0.65mm, IPC Medium Density"
  rrect50% 1.7x0.35 smd: 1(-2.85,0.975) 2(-2.85,0.325) 3(-2.85,-0.325) 4(-2.85,-0.975) 5(2.85,-0.975) 6(2.85,-0.325) 7(2.85,0.325) 8(2.85,0.975)
  silkscreen extent -2.97,-1.55 1.6,1.82, body extent -3.2,-1.55 3.2,1.55, height 1.07
WEEE_Minimum [mil] "WEEElie bin"
  silkscreen extent -95,-172 99,104
XTAL_ABM3 [mm] "Abracon recommended land pattern 12.28.10"
  rrect20% 1.9x2.4 smd: 1(-2.05,0) 2(2.05,0)
  silkscreen extent -2.67,-1.78 2.67,1.78, body extent -2.6,-1.7 2.6,1.7, height 1.3
YJM0003A [mm] "SMT, 3-Leads, Body 0.69x0.6mm"
  rrect80% 0.35x0.25 smd paste-0.2 mask-0.05: 1(-0.175,0.175) 2(-0.175,-0.175)
  rrect50% 0.25x0.2 on Bottom Paste: 1(-0.175,0.2) 2(-0.175,-0.2)
  rrect80% 0.25x0.6 smd paste-0.05 mask-0.05: 3(0.225,0)
  body extent -0.35,-0.3 0.35,0.3, height 0.35

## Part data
C1 C2 C3: library part capcc02687, "CAP CER 1UF 50V X7R 0805", Manufacturer="TDK Corporation", Operating Temperature="-55°C ~ 125°C", Ratings=-, Supplier Part Number 1=445-7547-1-ND, Temperature Coefficient=X7R, Tolerance=±10%, Voltage - Rated=50V
C4 C5: library part capcc03751, "CAP CER 1000PF 50V X7R 0603", Manufacturer="TDK Corporation", Operating Temperature="-55°C ~ 125°C", Ratings=AEC-Q200, Supplier Part Number 1=445-5659-1-ND, Temperature Coefficient=X7R, Tolerance=±10%, Voltage - Rated=50V
C6: library part capcc03515, "CAP CER 10UF 25V X5R 0805", Manufacturer="KYOCERA AVX", Operating Temperature="-55°C ~ 85°C", Ratings=-, Supplier Part Number 1=478-08053D106KAT4ACT-ND, Temperature Coefficient=X5R, Tolerance=±10%, Voltage - Rated=25V
C7 C8 C114 C116 C132: library part capcc03298, "CAP CER 4.7UF 10V X5R 0402", Manufacturer="TDK Corporation", Operating Temperature="-55°C ~ 85°C", Ratings=-, Supplier Part Number 1=445-13820-1-ND, Temperature Coefficient=X5R, Tolerance=±10%, Voltage - Rated=10V
C9 C34 C35 C36 C37 C38 C42 C43 C44 C45 C46 C84 C94: library part capcc09395, "CAP CER 22UF 10V X7S 0805", Manufacturer="TDK Corporation", Operating Temperature="-55°C ~ 125°C", Ratings=-, Supplier Part Number 1=445-14560-1-ND, Temperature Coefficient=X7S, Tolerance=±20%, Voltage - Rated=10V
C10: library part capcc04738, "CAP CER 3300PF 50V X7R 0402", Manufacturer="TDK Corporation", Operating Temperature="-55°C ~ 125°C", Ratings=AEC-Q200, Supplier Part Number 1=445-6891-1-ND, Temperature Coefficient=X7R, Tolerance=±10%, Voltage - Rated=50V
C11 C12 C13 C14 C15 C16 C17 C18 C100 C101 C102 C103: library part capcc01389, "CAP CER 0.1UF 16V X5R 0201", Manufacturer="TDK Corporation", Operating Temperature="-55°C ~ 85°C", Ratings=-, Supplier Part Number 1=445-7313-1-ND, Temperature Coefficient=X5R, Tolerance=±10%, Voltage - Rated=16V
C19 C48 C50 C80 C82 C91 C93 C104 C106 C113 C119 C120 C121 C122 C131 C134 C135 C136 C137 C138 C139 C140 C141 C142 C143 C144 C145 C146 C147 C148 C149 C150 C151 C152 C153 C154 C155 C156 C157 C158 C159 C177 C315 C316: library part capcc09401, "CAP CER 0.1UF 25V X7R 0402", Manufacturer=Murata, Operating Temperature="-55°C ~ 125°C", Ratings=-, Supplier Part Number 1=490-GRT155R71E104KE01JCT-ND, Temperature Coefficient=X7R, Tolerance=±10%, Voltage - Rated=25V
C20 C21: library part capcc09404, "CAP CER 47UF 25V X5R 1206", Manufacturer="TDK Corporation", Operating Temperature="-55°C ~ 85°C", Ratings=-, Supplier Part Number 1=445-8047-1-ND, Temperature Coefficient=X5R, Tolerance=±20%, Voltage - Rated=25V
C22 C23 C24 C25 C27 C28 C29 C30: library part capcc06824, "CAP CER 100UF 10V X5R 1206", Manufacturer="CAL-CHIP ELECTRONICS, INC.", Operating Temperature="-55°C ~ 85°C", Ratings=-, Supplier Part Number 1=2571-GMC31X5R107M10NTTR-ND, Temperature Coefficient=X5R, Tolerance=±20%, Voltage - Rated=10V
C26: library part capcc05508, "CAP CER 10000PF 16V X5R 0402", Manufacturer="KYOCERA AVX", Operating Temperature="-55°C ~ 85°C", Ratings=-, Supplier Part Number 1=478-0402YD103KAT2ACT-ND, Temperature Coefficient=X5R, Tolerance=±10%, Voltage - Rated=16V
C31: library part capcc03230, "CAP CER 2.2UF 10V X5R 0402", Manufacturer="KYOCERA AVX", Operating Temperature="-55°C ~ 85°C", Ratings=-, Supplier Part Number 1=478-CM05X5R225K10AHCT-ND, Temperature Coefficient=X5R, Tolerance=±10%, Voltage - Rated=10V
C32 C33 C40 C41 C49 C52 C81 C92 C105 C107: library part capcc03511, "CAP CER 10UF 25V X7S 0805", Manufacturer="TDK Corporation", Operating Temperature="-55°C ~ 125°C", Ratings=-, Supplier Part Number 1=445-181600-1-ND, Temperature Coefficient=X7S, Tolerance=±10%, Voltage - Rated=25V
C39 C47: library part capcc01693, "CAP CER 0.22UF 16V X5R 0402", Manufacturer="TDK Corporation", Operating Temperature="-55°C ~ 85°C", Ratings=AEC-Q200, Supplier Part Number 1=445-12172-1-ND, Temperature Coefficient=X5R, Tolerance=±20%, Voltage - Rated=16V
C51 C57 C59 C60 C61 C62 C63 C64 C69 C77 C83 C89: library part dcp00009, "CAP FEEDTHRU 1UF 20% 6.3V 0603", Current="4 A", Manufacturer="Murata Electronics", Operating Temperature="-55°C ~ 105°C", Supplier Part Number 1=490-6970-1-ND, Temperature Coefficient=-, Tolerance=±20%, Voltage - Rated=6.3V
C53 C54 C55 C56 C85 C86 C87 C88 C95 C96 C97 C98 C108 C109 C110 C111: "CAP CER 47UF 6.3V X5R 0603", Manufacturer=Murata, Operating Temperature="-55°C ~ 85°C", Ratings=-, Supplier Part Number 1=490-13247-1-ND, Temperature Coefficient=X5R, Tolerance=±20%, Voltage - Rated=6.3V
C58 C112: library part CeramicCap, "CAP CER 1UF 25V X5R 0402", Manufacturer="TDK Corporation", Operating Temperature="-55°C ~ 85°C", Ratings=-, Supplier Part Number 1=445-9066-1-ND, Temperature Coefficient=X5R, Tolerance=±10%, Voltage - Rated=25V
C65 C72 C73: library part capcc09325, "MLCC 0.1UF 16V X7R 0603", Manufacturer="Murata Electronics", Operating Temperature="-55°C ~ 125°C", Ratings=-, Supplier Part Number 1=490-GRM033Z71C104KE14JCT-ND, Temperature Coefficient=X7R, Tolerance=±10%, Voltage - Rated=16V
C66 C70 C71 C74 C78 C79: library part capcc03657, "CAP CER 10UF 10V X5R 0603", Manufacturer="KYOCERA AVX", Operating Temperature="-55°C ~ 85°C", Ratings=-, Supplier Part Number 1=478-10766-1-ND, Temperature Coefficient=X5R, Tolerance=±10%, Voltage - Rated=10V
C67 C75: library part capcc03112, "CAP CER 2.2UF 10V X5R 0402", Manufacturer="TDK Corporation", Operating Temperature="-55°C ~ 85°C", Ratings=-, Supplier Part Number 1=445-7392-1-ND, Temperature Coefficient=X5R, Tolerance=±10%, Voltage - Rated=10V
C68 C76: library part capcc09264, "CAP CER 1UF 10V X5R 0201", Manufacturer="Murata Electronics", Operating Temperature="-55°C ~ 85°C", Ratings=-, Supplier Part Number 1=490-GRM033R61A105ME44DCT-ND, Temperature Coefficient=X5R, Tolerance=±20%, Voltage - Rated=10V
C90 C99: library part capcc03139, "CAP CER 4.7UF 10V X5R 0402", Manufacturer="TDK Corporation", Operating Temperature="-55°C ~ 85°C", Ratings=-, Supplier Part Number 1=445-175214-1-ND, Temperature Coefficient=X5R, Tolerance=±10%, Voltage - Rated=10V
C115 C117 C123 C124 C125 C126 C127 C128: library part capcc01256, "CAP CER 0.1UF 25V X5R 0402", Manufacturer="KYOCERA AVX", Operating Temperature="-55°C ~ 85°C", Ratings=-, Supplier Part Number 1=478-7869-1-ND, Temperature Coefficient=X5R, Tolerance=±10%, Voltage - Rated=25V
C118: library part capcc03130, "CAP CER 3.3UF 10V X5R 0603", Manufacturer="TDK Corporation", Operating Temperature="-55°C ~ 85°C", Ratings=AEC-Q200, Supplier Part Number 1=445-7879-1-ND, Temperature Coefficient=X5R, Tolerance=±10%, Voltage - Rated=10V
C129 C130: library part capcc08580, "CAP CER 18PF 25V C0H 0201", Manufacturer="Murata Electronics", Operating Temperature="-55°C ~ 125°C", Ratings=-, Temperature Coefficient=C0H, Tolerance=±5%, Voltage - Rated=25V
C133: library part capcc02805, "CAP CER 1UF 25V X5R 0402", Manufacturer="KYOCERA AVX", Operating Temperature="-55°C ~ 85°C", Ratings=-, Supplier Part Number 1=478-CM05X5R105K25AHCT-ND, Temperature Coefficient=X5R, Tolerance=±10%, Voltage - Rated=25V
C160 C161 C162 C163 C164 C165 C166 C167 C168 C169 C170 C171 C172 C173 C174 C175 C217 C236 C237 C238 C239 C240 C241 C242 C243 C244 C245 C246 C247 C248 C249 C250 C251 C252 C253 C254 C255 C256 C257 C258 C259 C260 C261 C262 C263 C264 C265 C266 C267 C268 C269 C270 C271 C272 C273 C274 C275 C276 C277 C278 C279 C280 C281 C282 C283 C284 C285 C286 C287 C288 C289 C290 C291 C292 C293 C294 C295 C296 C297 C298 C299 C300 C301 C302 C303 C304 C305 C306 C307 C308 C309 C310 C311 C312 C313 C314: library part capcc09263, "CAP CER 0.1UF 16V X7R 0201", Manufacturer="Murata Electronics", Operating Temperature="-55°C ~ 125°C", Ratings=-, Supplier Part Number 1=490-GRM033Z71C104KE14DCT-ND, Temperature Coefficient=X7R, Tolerance=±10%, Voltage - Rated=16V
C176: library part capcc03566, "CAP CER 10UF 10V X5R 0603", Manufacturer="TDK Corporation", Operating Temperature="-55°C ~ 85°C", Ratings=-, Supplier Part Number 1=445-C1608X5R1A106K080ACCT-ND, Temperature Coefficient=X5R, Tolerance=±10%, Voltage - Rated=10V
C178 C179 C180 C181 C182 C183 C184 C185 C186 C187 C188 C189 C190 C191 C192 C193 C194 C195 C196 C197 C198 C199 C200 C201 C202 C203 C204 C205 C206 C207 C208 C209 C210 C211 C212 C213 C214 C215 C216 C220 C221 C222 C223 C224 C225 C228 C229 C230 C231 C232 C233: library part 0201RFCaps0693, "Broadband Capacitors", Alt Manufacturer="Murata Electronics", Alt PartNumber=GRM033C71C104ME14D, Manufacturer="Passive Plus", Operating Temperature="-55°C ~ 125°C", Temperature Coefficient="C0G, NP0", Tolerance=±10%, Voltage - Rated=16V
C218: library part capcc08503, "CAP CER MLCC", Manufacturer="Murata Electronics", Operating Temperature="-55°C ~ 125°C", Ratings=-, Supplier Part Number 1=490-GRM033R71C101JA01DCT-ND, Temperature Coefficient=X7R, Tolerance=±5%, Voltage - Rated=16V
C219: library part CMP-0064970-1, "CAP, CERM, 0.1 uF, 16 V,+/- 10%, X7R, 0201", Cap_Case=0201, Manufacturer=MuRata, Supplier Part Number 1=81-GRM033Z71C104KE4D, TempCo=X7R, Tolerance_%=10%, Value1=Unknown, Value2=16V, ValueDisplayed=0.1uF
C226 C227 C234 C235: library part 0201RFCaps0050, "CAP CER 0.5PF 50V C0G/NP0 0201", Alt Manufacturer=-, Manufacturer="Murata Electronics", Operating Temperature="-55°C ~ 125°C", Temperature Coefficient="C0G, NP0", Tolerance=±0.05pF, Voltage - Rated=50V
D1 D4: library part cmp00247, "LED GREEN CLEAR CHIP SMD", Alt Manufacturer=-, Color=Green, Current Rating (Amps)=20mA, Manufacturer="Lite-On Inc.", Supplier Part Number 1=160-1888-1-ND, Voltage - Forward (Vf) (Typ)=3.2V
D2: library part cmp00440, "24.4V Clamp 24.6A Ipp Tvs Diode", Alt Manufacturer=-, Manufacturer=Littlefuse, Supplier Part Number 1=SMBJ15CALFCT-ND
D3: library part cmp00438, "DIODE SCHOTTKY 30V 1A SOD123", Alt Manufacturer="Rohm Semiconductor", Alt PartNumber=RB160M-30TR, Color=-, Manufacturer=Onsemi, Supplier Part Number 1=MBR130T1GOSCT-ND
D5: "Diode Array 1 Pair Common Cathode 20 V 400mA (DC)", Alt Manufacturer=-, Manufacturer="Diodes Inc", Supplier Part Number 1=SDM40E20LC-7DICT-ND
D6 D7: library part cmp00244, "LED RED CLEAR CHIP SMD", Alt Manufacturer=-, Color=Red, Current Rating (Amps)=20mA, Manufacturer="Lite-On Inc.", Supplier Part Number 1=160-1436-1-ND, Voltage - Forward (Vf) (Typ)=2V
F1: library part cmp00325, "EMI Filter Circuits 40 DB 50V 10A", Alt Manufacturer=-, Manufacturer="Murata Electronics", Supplier Part Number 1=81-BNX002-11
FB1 FB2: library part dcp00004, "8.5 Ohms @ 100 MHz 1 Power Line Ferrite Bead 0603 (1608 Metric) 8A 4mOhm", Current=8A, Manufacturer=Murata, Operating Temperature="-55°C ~ 125°C", Supplier Part Number 1=490-BLE18PS080SN1DCT-ND, Temperature Coefficient=-
FB3 FB4 FB5 FB6: library part dcp00613, "FERRITE BEAD 600 OHM 1206 1LN", Current=2.9A, Manufacturer="Murata Electronics", Operating Temperature="-55°C ~ 125°C", Supplier Part Number 1=490-16533-1-ND, Temperature Coefficient=-
FB7 FB8: library part dcp00209, "0402 (1005) 150OHM (TYP.) 1000MA", Current=1A, Manufacturer="Murata Electronics", Operating Temperature="-40°C ~ 85°C", Supplier Part Number 1=490-18375-1-ND, Temperature Coefficient=-
FC1: "Feed through capactior 27uF", Current=6A, Manufacturer=Murata, Operating Temperature="-40°C ~ 85°C", PartNumber=NFM31PC276B0J3L, Supplier Part Number 1=490-6984-1-ND, Temperature Coefficient=-, Tolerance=±20%, Voltage - Rated=6.3V
FID1 FID2 FID3: library part cmp00099, "Fiducial", Alt Manufacturer=-
H1 H3: "Hex Standoff Threaded M3 Nylon 1.260\" (32.00mm) Natural", Alt Manufacturer=-, Manufacturer="Essentra Components", Supplier Part Number 1=RPC3620-ND
H5 H6: library part cmp00098, "Hex Standoff Threaded #2-56 Aluminum 0.188\" (4.78mm) 3/16\"", Alt Manufacturer=-, Manufacturer="RAF Electronic Hardware", Supplier Part Number 1=36-1797A-ND
J1: "FMC+, High Density Array, Male / EVM Connector 40x14", Alt Manufacturer=-, Manufacturer=Samtec, Supplier Part Number 1=SAM9173-ND
J2: library part cmp00022, "Power Jack, mini, 2.1mm OD, R/A, TH", Alt Manufacturer=-, Manufacturer=Switchcraft, Supplier Part Number 1=SC1313-ND
J3: "USB - C (Type - C) USB 2.0 Receptacle Connector 24 Position Surface Mount, Right Angle; Through Hole", Manufacturer=GCT, Supplier Part Number 1=2073-USB4105-GF-ACT-ND
J4 J5: "SMA Connector Jack, Female Socket 50Ohm Surface Mount, Through Hole Solder", Alt Manufacturer=-, Manufacturer="Amphenol RF", Supplier Part Number 1=ACX1962-ND
J7 J9 J13 J14 J15 J16 J17 J18: library part cmp00522, "2.92mm Connector Receptacle, Female Socket 50 Ohms Board Edge, End Launch Compression", Alt Manufacturer=HiRose, Color=-, Manufacturer=KonnectRF, PartNumber=KCC198709, Supplier Part Number 1=H125498-ND
J8 J10 J11 J12: library part cmp00032, "SMP Connector Plug, Male Pin 50Ohm Surface Mount Solder", Alt Manufacturer=-, Manufacturer=Molex, Supplier Part Number 1=WM3891CT-ND, Voltage_V=335V
LBL1: library part cmp00106, "Thermal Transfer Printable Labels, 0.650\" W x 0.200\" H - 10,000 per roll", Alt Manufacturer=-, Manufacturer=Brady, Supplier Part Number 1=2267-THT-14-423-10-ND
LOGO1: library part cmp00100, "IEC 61010-1 Hot Surface Warning", Alt Manufacturer=-, PartNumber=IEC_HotSurface
Logo2: library part cmp00102, "FCC_disclaimer", Alt Manufacturer=-
Logo3: library part cmp00317, Alt Manufacturer=-, PartNumber="ESD Logo"
Logo4: library part cmp00101, Alt Manufacturer=-, PartNumber=WEEE_Minimum
LOGO5: library part cmp00103, "CE_Mark", Alt Manufacturer=-
Logo6 Logo8: library part cmp00104, "Texas Instrument Corporate Signature", Alt Manufacturer=-, PartNumber="TI Bug"
Logo7: library part cmp00105, "FDL", Alt Manufacturer=-
PP1 PP2 PP3 PP4 PP5 PP6 PP7 PP8 PP9 PP10 PP11 PP14 PP15 PP16 PP17 PP18 PP19 PP20 PP21 PP22 PP23 PP24 PP25 PP26 PP27 PP28 PP29 PP30 PP31 PP32 PP33 PP34 PP35 PP36 PP37 PP38 PP39 PP40 PP41 PP42 PP43 PP44 PP45 PP46 PP47 PP48 PP49 PP50 PP51 PP52 PP53 PP54 PP55 PP56 PP57 PP58 PP59 PP60 PP61 PP62 PP63 PP64 PP65 PP66 PP67 PP68: "Probe Point that can be used in lue of a test point", Alt Manufacturer=-
PP12 PP13: library part cmp00025, "Probe Point that can be used in lue of a test point", Alt Manufacturer=-
Q1: library part cmp00159, "MOSFET, N-CH, 20 V, 10 A", Alt Manufacturer=-, Manufacturer="Texas Instruments", Supplier Part Number 1=296-39992-1-ND
Q2 Q3: "MOSFET, P-CH, -20 V, -1.7 A, YJM0003A (PICOSTAR-3)", Alternate Manufacturer=None, Manufacturer="Texas Instruments", Value1=0.15, Value2="0.7 nC"
R1: library part RSMD040200026, "RES SMD 1M OHM 1% 1/10W 0402", Manufacturer="Panasonic Electronic Components", Operating Temperature="-55°C ~ 155°C", Power (Watts)="0.1W, 1/10W", Ratings=AEC-Q200, Resistance="1 MΩ", Supplier Part Number 1=P1.00MLCT-ND, Temperature Coefficient=±100ppm/°C, Tolerance=±1%
R2: library part RSMD040203665, "RES SMD 76.8K OHM 1% 1/10W 0402", Manufacturer="Panasonic Electronic Components", Operating Temperature="-55°C ~ 155°C", Power (Watts)="0.1W, 1/10W", Ratings=AEC-Q200, Resistance="76.8 kΩ", Supplier Part Number 1=P76.8KLCT-ND, Temperature Coefficient=±100ppm/°C, Tolerance=±1%
R3: library part RSMD080501129, "RES SMD 4.7K OHM 1% 1/8W 0805", Manufacturer="Panasonic Electronic Components", Operating Temperature="-55°C ~ 155°C", Power (Watts)="0.125W, 1/8W", Ratings=AEC-Q200, Resistance="4.7 kΩ", Supplier Part Number 1=P4.70KCCT-ND, Temperature Coefficient=±100ppm/°C, Tolerance=±1%
R4: library part RSMD040200945, "RES SMD 162K OHM 1% 1/10W 0402", Manufacturer="Panasonic Electronic Components", Operating Temperature="-55°C ~ 155°C", Power (Watts)="0.1W, 1/10W", Ratings=AEC-Q200, Resistance="162 kΩ", Supplier Part Number 1=P162KLCT-ND, Temperature Coefficient=±100ppm/°C, Tolerance=±1%
R5 R8 R9 R20 R26 R33 R34 R38 R39 R44 R45 R68 R69 R79 R82 R90 R91 R97 R100 R111 R112 R113 R118 R194: library part RSMD040200314, "RES SMD 10K OHM 1% 1/10W 0402", Manufacturer="Panasonic Electronic Components", Operating Temperature="-55°C ~ 155°C", Power (Watts)="0.1W, 1/10W", Ratings=AEC-Q200, Resistance="10 kΩ", Supplier Part Number 1=P10.0KLCT-ND, Temperature Coefficient=±100ppm/°C, Tolerance=±1%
